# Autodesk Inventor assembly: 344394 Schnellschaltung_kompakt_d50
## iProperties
Company: Mayer & Müller AG Schaltgeräte
Created: 2006-10
Part Number: 344394 Schnellschaltung_kompakt_d50
Document SubType Name: Assembly
Designer: Natti_01
Description: Schnellschaltung
Cost Center: 7,565 kg
Authority: 1267445 mm^3
Mass: 11280.2 g
Surface Area: 4768.98 cm^2
Volume: 1651.49 cm^3
Density: 6.83033 g/cm^3
SaveDate: 2006-11-07
SaveTime: 20:08
TotalMass: 7,565 kg
TotalVolume: 1267445 mm^3
Author: Natti_01
